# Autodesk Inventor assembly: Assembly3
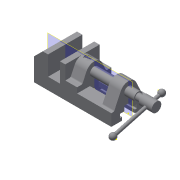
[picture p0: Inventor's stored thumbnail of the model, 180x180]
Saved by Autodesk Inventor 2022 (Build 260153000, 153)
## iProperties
Created: 2016-05
Part Number: Assembly3
Document SubType Name: Assembly
Designer: Sandeep
Author: Sandeep
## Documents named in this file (11)
- D:\PROJECTS_2021\Resources\Tutorial Files\c09_Inv_2022_tut\c09_Inv_2021_tut\c09_Inv_tut_2021\c09_tut04_inv\Bench vice assembly.iam
- D:\PROJECTS_2021\Resources\Tutorial Files\c09_Inv_2022_tut\c09_Inv_2021_tut\c09_Inv_tut_2021\c09_tut04_inv\Base.ipt
- D:\PROJECTS_2021\Resources\Tutorial Files\c09_Inv_2022_tut\c09_Inv_2021_tut\c09_Inv_tut_2021\c09_tut04_inv\base plate.ipt
- D:\PROJECTS_2021\Resources\Tutorial Files\c09_Inv_2022_tut\c09_Inv_2021_tut\c09_Inv_tut_2021\c09_tut04_inv\vice jaw.ipt
- D:\PROJECTS_2021\Resources\Tutorial Files\c09_Inv_2022_tut\c09_Inv_2021_tut\c09_Inv_tut_2021\c09_tut04_inv\jaw screw.ipt
- D:\PROJECTS_2021\Resources\Tutorial Files\c09_Inv_2022_tut\c09_Inv_2021_tut\c09_Inv_tut_2021\c09_tut04_inv\clamping plate.ipt
- D:\PROJECTS_2021\Resources\Tutorial Files\c09_Inv_2022_tut\c09_Inv_2021_tut\c09_Inv_tut_2021\c09_tut04_inv\Screw Bar.ipt
- D:\PROJECTS_2021\Resources\Tutorial Files\c09_Inv_2022_tut\c09_Inv_2021_tut\c09_Inv_tut_2021\c09_tut04_inv\bar globes.ipt
- D:\PROJECTS_2021\Resources\Tutorial Files\c09_Inv_2022_tut\c09_Inv_2021_tut\c09_Inv_tut_2021\c09_tut04_inv\set scew 1.ipt
- D:\PROJECTS_2021\Resources\Tutorial Files\c09_Inv_2022_tut\c09_Inv_2021_tut\c09_Inv_tut_2021\c09_tut04_inv\set scew 2.ipt
- D:\PROJECTS_2021\Resources\Tutorial Files\c09_Inv_2022_tut\c09_Inv_2021_tut\c09_Inv_tut_2021\c09_tut04_inv\Oval Filister.ipt
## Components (16 placed, 10 different names)
1. Base:1 — Slider:1, Cylindrical:1, Insert:10, Mate:15, Mate:16, Mate:17, Mate:18, Mate:19, Mate:21, Mate:23
2. base plate:1 — Insert:10, Mate:15, Mate:20, Mate:22
3. base plate:2 — Mate:16, Mate:17, Mate:18, Mate:24, Mate:25, Mate:26
4. vice jaw:1 — Slider:1, Mate:1, Mate:2, Mate:12, Mate:13, Mate:14, Insert:11
5. jaw screw:1 — Cylindrical:1, Mate:1, Cylindrical:2
6. clamping plate:1 — Mate:2, Mate:27, Mate:28, Mate:29, Mate:30, Insert:11
7. Screw Bar:1 — Cylindrical:2, Rigid:2, Rigid:3
8. bar globes:1 — Rigid:2
9. bar globes:2 — Rigid:3
10. Oval Filister:1 — Mate:12, Mate:13, Mate:14
11. set scew 1:1 — Mate:19, Mate:20
12. set scew 1:2 — Mate:21, Mate:22
13. set scew 1:3 — Mate:23, Mate:24
14. set scew 1:4 — Mate:25, Mate:26
15. set scew 2:1 — Mate:27, Mate:28
16. set scew 2:2 — Mate:29, Mate:30
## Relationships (28: Mate 21, CylindricalJoint 2, WeldJoint 2, Insert 2, TranslationJoint 1)
- Slider:1 [TranslationJoint]: Base:1 ↔ vice jaw:1
- Cylindrical:1: Base:1 ↔ jaw screw:1
- Mate:1: vice jaw:1 ↔ jaw screw:1
- Cylindrical:2: jaw screw:1 ↔ Screw Bar:1
- Rigid:2 [WeldJoint]: Screw Bar:1 ↔ bar globes:1
- Rigid:3 [WeldJoint]: Screw Bar:1 ↔ bar globes:2
- Mate:2: vice jaw:1 ↔ clamping plate:1
- Mate:12: vice jaw:1 ↔ Oval Filister:1
- Mate:13: vice jaw:1 ↔ Oval Filister:1
- Mate:14: vice jaw:1 ↔ Oval Filister:1
- Insert:10: Base:1 ↔ base plate:1
- Mate:15: Base:1 ↔ base plate:1
- Mate:16: Base:1 ↔ base plate:2
- Mate:17: Base:1 ↔ base plate:2
- Mate:18: Base:1 ↔ base plate:2
- Mate:19: Base:1 ↔ set scew 1:1
- Mate:20: base plate:1 ↔ set scew 1:1
- Mate:21: Base:1 ↔ set scew 1:2
- Mate:22: base plate:1 ↔ set scew 1:2
- Mate:23: Base:1 ↔ set scew 1:3
- Mate:24: base plate:2 ↔ set scew 1:3
- Mate:25: base plate:2 ↔ set scew 1:4
- Mate:26: base plate:2 ↔ set scew 1:4
- Mate:27: clamping plate:1 ↔ set scew 2:1
- Mate:28: clamping plate:1 ↔ set scew 2:1
- Mate:29: clamping plate:1 ↔ set scew 2:2
- Mate:30: clamping plate:1 ↔ set scew 2:2
- Insert:11: vice jaw:1 ↔ clamping plate:1
